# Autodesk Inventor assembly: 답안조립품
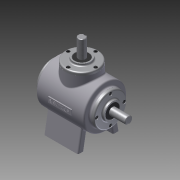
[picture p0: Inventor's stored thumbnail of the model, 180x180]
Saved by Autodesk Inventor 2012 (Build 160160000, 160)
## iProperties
Created: 2015-01
Part Number: 답안조립품
Document SubType Name: Assembly
Designer: Owner
Author: Owner
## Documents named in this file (15)
- C:\Documents and Settings\Owner\바탕 화면\450105V1012\답안조립품.iam
- C:\Documents and Settings\Owner\바탕 화면\450105V1012\1 본체.ipt
- C:\Documents and Settings\Owner\바탕 화면\450105V1012\오일실.ipt
- C:\Documents and Settings\Owner\바탕 화면\450105V1012\베어링 6203.ipt
- C:\Documents and Settings\Owner\바탕 화면\450105V1012\커버.ipt
- C:\Documents and Settings\Owner\바탕 화면\450105V1012\서브 축.ipt
- 서브 축.ipt
- C:\Documents and Settings\Owner\바탕 화면\450105V1012\서브 베벨기어.ipt
- C:\Documents and Settings\Owner\바탕 화면\450105V1012\키 4x4.ipt
- C:\Documents and Settings\Owner\바탕 화면\450105V1012\커버2.ipt
- C:\Documents and Settings\Owner\바탕 화면\450105V1012\메인 베벨기어.ipt
- C:\Documents and Settings\Owner\바탕 화면\450105V1012\메인 축.ipt
- 메인 축.ipt
- C:\Documents and Settings\Owner\바탕 화면\450105V1012\키 5x5.ipt
- C:\Documents and Settings\Owner\바탕 화면\450105V1012\M4.ipt
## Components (13 placed, 2 different names)
1. 1 본체:1
2. M4:1 — 각도:6
3. M4:2 — 각도:5
4. M4:4
5. M4:5
6. M4:6
7. M4:7
8. M4:8
9. M4:9
10. M4:3 — 각도:7
11. M4:10
12. M4:11
13. M4:12
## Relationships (3: Angle 3)
- 각도:5 [Angle]: M4:2
- 각도:6 [Angle]: M4:1
- 각도:7 [Angle]: M4:3
